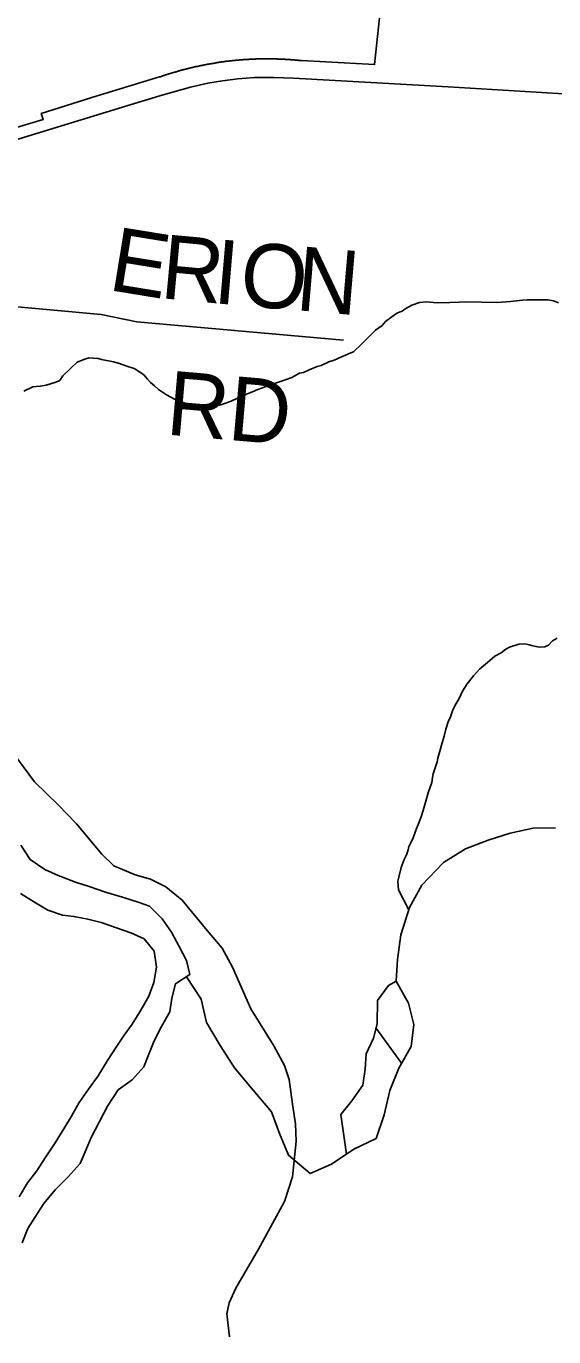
# Model space of a CAD drawing. Extents: x 0 to 34, y 0 to 22.
# Drawn here: x 5.777 to 6.245, y 15.409 to 16.571 of the extents above; entities that cross this region are included whole.
import ezdxf

# ---------------------------------------------------------------- set-up
doc = ezdxf.new("R2010")
doc.units = 0
for name, color, linetype in [('GM_X_Corporation', 7, 'Continuous'), ('GM_X_Major_River', 7, 'Continuous'), ('GM_X_Minor_River', 7, 'Continuous'), ('GM_X_Rail_Line', 7, 'Continuous'), ('GM_X_Township_Road', 7, 'Continuous'), ('GM_X_Township_Road_Text', 7, 'Continuous')]:
    doc.layers.add(name, color=color, linetype=linetype)

msp = doc.modelspace()

# ---------------------------------------------------------------- linework, layer by layer
at = {"layer": 'GM_X_Corporation'}
msp.add_lwpolyline([(6.0913, 16.5869), (6.0859, 16.5372), (6.0212, 16.5407), (6.0206, 16.5407), (6.02, 16.5408), (6.0193, 16.5409), (6.0187, 16.5409), (6.0181, 16.541), (6.0175, 16.541), (6.0169, 16.5411), (6.0163, 16.5412), (6.0156, 16.5412), (6.015, 16.5413), (6.0144, 16.5413), (6.0138, 16.5414), (6.0132, 16.5414), (6.0126, 16.5415), (6.0119, 16.5415), (6.0113, 16.5416), (6.0107, 16.5416), (6.0101, 16.5416), (6.0095, 16.5417), (6.0088, 16.5417), (6.0082, 16.5418), (6.0076, 16.5418), (6.007, 16.5418), (6.0064, 16.5419), (6.0058, 16.5419), (6.0051, 16.5419), (6.0045, 16.542), (6.0039, 16.542), (6.0033, 16.542), (6.0027, 16.5421), (6.002, 16.5421), (6.0014, 16.5421), (6.0008, 16.5421), (6.0002, 16.5421), (5.9996, 16.5422), (5.999, 16.5422), (5.9983, 16.5422), (5.9977, 16.5422), (5.9971, 16.5422), (5.9965, 16.5422), (5.9959, 16.5423), (5.9952, 16.5423), (5.9946, 16.5423), (5.994, 16.5423), (5.9934, 16.5423), (5.9928, 16.5423), (5.9921, 16.5423), (5.9915, 16.5423), (5.9909, 16.5423), (5.9903, 16.5423), (5.9897, 16.5423), (5.989, 16.5423), (5.9884, 16.5423), (5.9878, 16.5423), (5.9872, 16.5423), (5.9866, 16.5423), (5.986, 16.5423), (5.9853, 16.5423), (5.9847, 16.5423), (5.9841, 16.5422), (5.9835, 16.5422), (5.9829, 16.5422), (5.9822, 16.5422), (5.9816, 16.5422), (5.981, 16.5422), (5.9804, 16.5421), (5.9798, 16.5421), (5.9791, 16.5421), (5.9785, 16.5421), (5.9779, 16.542), (5.9773, 16.542), (5.9767, 16.542), (5.9761, 16.5419), (5.9754, 16.5419), (5.9748, 16.5419), (5.9742, 16.5418), (5.9736, 16.5418), (5.973, 16.5418), (5.9723, 16.5417), (5.9717, 16.5417), (5.9711, 16.5417), (5.9705, 16.5416), (5.9699, 16.5416), (5.9693, 16.5415), (5.9686, 16.5415), (5.968, 16.5414), (5.9674, 16.5414), (5.9668, 16.5413), (5.9662, 16.5413), (5.9656, 16.5412), (5.9649, 16.5412), (5.9643, 16.5411), (5.9637, 16.5411), (5.9631, 16.541), (5.9625, 16.5409), (5.9619, 16.5409), (5.9612, 16.5408), (5.9606, 16.5408), (5.96, 16.5407), (5.9594, 16.5406), (5.9588, 16.5406), (5.9582, 16.5405), (5.9575, 16.5404), (5.9569, 16.5403), (5.9563, 16.5403), (5.9557, 16.5402), (5.9551, 16.5401), (5.9545, 16.5401), (5.9539, 16.54), (5.9532, 16.5399), (5.9526, 16.5398), (5.952, 16.5397), (5.9514, 16.5396), (5.9508, 16.5396), (5.9502, 16.5395), (5.9496, 16.5394), (5.949, 16.5393), (5.9483, 16.5392), (5.9477, 16.5391), (5.9471, 16.539), (5.9465, 16.5389), (5.9459, 16.5388), (5.9453, 16.5387), (5.9447, 16.5386), (5.9441, 16.5385), (5.9434, 16.5384), (5.9428, 16.5383), (5.9422, 16.5382), (5.9416, 16.5381), (5.941, 16.538), (5.9404, 16.5379), (5.9398, 16.5378), (5.9392, 16.5377), (5.9386, 16.5376), (5.938, 16.5375), (5.9373, 16.5374), (5.9367, 16.5373), (5.9361, 16.5371), (5.9355, 16.537), (5.9349, 16.5369), (5.9343, 16.5368), (5.9337, 16.5367), (5.9331, 16.5365), (5.9325, 16.5364), (5.9319, 16.5363), (5.9313, 16.5362), (5.9307, 16.536), (5.9301, 16.5359), (5.9295, 16.5358), (5.9289, 16.5356), (5.9282, 16.5355), (5.9276, 16.5354), (5.927, 16.5352), (5.9264, 16.5351), (5.9258, 16.535), (5.9252, 16.5348), (5.9246, 16.5347), (5.924, 16.5345), (5.9234, 16.5344), (5.9228, 16.5343), (5.9222, 16.5341), (5.9216, 16.534), (5.921, 16.5338), (5.9204, 16.5337), (5.9198, 16.5335), (5.9192, 16.5334), (5.9186, 16.5332), (5.918, 16.533), (5.9174, 16.5329), (5.9168, 16.5327), (5.9162, 16.5326), (5.9156, 16.5324), (5.915, 16.5323), (5.9144, 16.5321), (5.9138, 16.5319), (5.9132, 16.5318), (5.9126, 16.5316), (5.912, 16.5314), (5.9114, 16.5313), (5.9109, 16.5311), (5.9103, 16.5309), (5.9097, 16.5307), (5.9091, 16.5306), (5.9085, 16.5304), (5.9079, 16.5302), (5.9073, 16.53), (5.9067, 16.5299), (5.9061, 16.5297), (5.9055, 16.5295), (5.9049, 16.5293), (5.9043, 16.5291), (5.9037, 16.5289), (5.9031, 16.5288), (5.9026, 16.5286), (5.902, 16.5284), (5.9014, 16.5282), (5.9008, 16.528), (5.9002, 16.5278), (5.8996, 16.5276), (5.899, 16.5274), (5.8984, 16.5272), (5.8979, 16.527), (5.8973, 16.5268), (5.8967, 16.5266), (5.8961, 16.5264), (5.8955, 16.5262), (5.8606, 16.5156), (5.8401, 16.5094), (5.7906, 16.4938), (5.7923, 16.4886), (5.6263, 16.4388)], dxfattribs=at)
at = {"layer": 'GM_X_Major_River'}
for points in [[(5.7725, 15.845), (5.7806, 15.8323), (5.7938, 15.8237), (5.8055, 15.8182), (5.821, 15.8123), (5.8331, 15.8086), (5.8474, 15.8035), (5.8625, 15.799), (5.8765, 15.7946), (5.8864, 15.791), (5.8976, 15.7798), (5.9061, 15.7679), (5.9127, 15.7553), (5.9194, 15.743), (5.9222, 15.7304), (5.9096, 15.7223), (5.9063, 15.7094), (5.9046, 15.6973), (5.8972, 15.6845), (5.8905, 15.6717), (5.8854, 15.6584), (5.8814, 15.6486), (5.871, 15.637), (5.8587, 15.6281), (5.8493, 15.6138), (5.8348, 15.586), (5.8305, 15.5754), (5.8249, 15.5629), (5.8145, 15.551), (5.8029, 15.5397), (5.7928, 15.5274), (5.785, 15.515), (5.7788, 15.5052), (5.7737, 15.4927)], [(5.7722, 15.8024), (5.7846, 15.7946), (5.7963, 15.7876), (5.8095, 15.7832), (5.8193, 15.7819), (5.8318, 15.7794), (5.8436, 15.7765), (5.8572, 15.7718), (5.87, 15.7674), (5.8817, 15.7622), (5.8906, 15.7511), (5.8927, 15.737), (5.8902, 15.7233), (5.8858, 15.7113), (5.8788, 15.6988), (5.871, 15.6864), (5.864, 15.6767), (5.8574, 15.6669), (5.8492, 15.6541), (5.841, 15.6406), (5.8325, 15.6289), (5.8243, 15.6169), (5.8173, 15.6049), (5.8114, 15.5951), (5.8028, 15.5812), (5.7939, 15.568), (5.7865, 15.5564), (5.7783, 15.5459), (5.7709, 15.5334)]]:
    msp.add_lwpolyline(points, dxfattribs=at)
at = {"layer": 'GM_X_Minor_River'}
for points in [[(5.8945, 16.2491), (5.9017, 16.2444), (5.9092, 16.2404), (5.9145, 16.2384), (5.919, 16.2365), (5.9255, 16.2352), (5.9316, 16.2347), (5.9361, 16.2343), (5.9392, 16.2342), (5.9449, 16.2345), (5.9498, 16.2355), (5.959, 16.2388), (5.9644, 16.2414), (5.9674, 16.2424), (5.9724, 16.245), (5.9778, 16.2472), (5.9824, 16.249), (5.9889, 16.2516), (5.9981, 16.2548), (6.0026, 16.2563), (6.0126, 16.2599), (6.0195, 16.2636), (6.0229, 16.2643), (6.0279, 16.2665), (6.0352, 16.2694), (6.0386, 16.2705), (6.0455, 16.2738), (6.0501, 16.2752), (6.0566, 16.2781), (6.0597, 16.2792), (6.0635, 16.2811), (6.0673, 16.2825), (6.0743, 16.2892), (6.0805, 16.2956), (6.0867, 16.3016), (6.0928, 16.306), (6.0955, 16.3094), (6.1013, 16.3135), (6.1063, 16.3172), (6.1105, 16.3186), (6.1136, 16.3208), (6.119, 16.3238), (6.1259, 16.3263), (6.1316, 16.327), (6.1414, 16.3261), (6.1528, 16.3262), (6.1608, 16.3265), (6.1669, 16.3268), (6.1947, 16.3263), (6.2065, 16.3272), (6.2171, 16.3282), (6.2213, 16.3285), (6.2285, 16.3287), (6.2396, 16.3285), (6.2445, 16.3277), (6.249, 16.3261)], [(5.7752, 16.2477), (5.7832, 16.2514), (5.7862, 16.2517), (5.7897, 16.252), (5.795, 16.2531), (5.8034, 16.2556), (5.8069, 16.2571), (5.8096, 16.2612), (5.8169, 16.2679), (5.8223, 16.2735), (5.8254, 16.2746), (5.8292, 16.276), (5.8327, 16.2771), (5.841, 16.2766), (5.8441, 16.2758), (5.8547, 16.2737), (5.86, 16.2721), (5.8656, 16.2701), (5.8728, 16.2677), (5.8785, 16.2642), (5.8818, 16.2618), (5.8848, 16.2583), (5.8874, 16.2553), (5.8908, 16.2525), (5.8945, 16.2491)], [(6.1163, 15.7879), (6.1072, 15.8055), (6.1066, 15.8131), (6.1074, 15.8169), (6.1095, 15.8252), (6.1122, 15.8324), (6.1142, 15.8366), (6.1158, 15.8411), (6.1162, 15.8441), (6.1198, 15.8509), (6.123, 15.86), (6.1246, 15.8634), (6.1273, 15.8702), (6.1289, 15.8758), (6.1314, 15.8842), (6.1334, 15.8914), (6.1366, 15.9008), (6.1374, 15.905), (6.1379, 15.9084), (6.1414, 15.919), (6.1419, 15.9224), (6.1439, 15.9284), (6.1459, 15.936), (6.1475, 15.9417), (6.1492, 15.9481), (6.1512, 15.9545), (6.1531, 15.959), (6.1551, 15.9643), (6.1575, 15.9692), (6.161, 15.9753), (6.1638, 15.9817), (6.1681, 15.9881), (6.1735, 15.9952), (6.1789, 16.0012), (6.1859, 16.0071), (6.1924, 16.0127), (6.1982, 16.0157), (6.2024, 16.019), (6.2055, 16.0208), (6.2139, 16.0234), (6.2192, 16.0236), (6.223, 16.0228), (6.2261, 16.022), (6.2291, 16.0212), (6.2321, 16.0208), (6.2367, 16.0211), (6.2401, 16.0225), (6.2436, 16.0263), (6.2478, 16.0288)], [(5.9193, 15.7285), (5.9323, 15.7085), (5.9369, 15.688), (5.949, 15.6675), (5.9619, 15.6477), (5.9783, 15.628), (5.9946, 15.6086), (6.0018, 15.5896), (6.0098, 15.5702), (6.0288, 15.5539), (6.0478, 15.5623), (6.0675, 15.5756), (6.0873, 15.5851), (6.0945, 15.606), (6.0994, 15.6276), (6.1074, 15.6474), (6.1184, 15.6667), (6.1207, 15.6861), (6.1161, 15.7051), (6.1051, 15.7245), (6.1062, 15.7439), (6.1093, 15.7655), (6.1169, 15.7898), (6.1279, 15.8096), (6.1469, 15.8297), (6.1666, 15.8419), (6.1867, 15.8495), (6.2061, 15.8559), (6.2266, 15.8601), (6.2464, 15.8605)], [(6.1051, 15.7245), (6.0983, 15.7206), (6.0885, 15.7075), (6.0882, 15.6866), (6.0849, 15.6741), (6.0786, 15.6602), (6.0776, 15.6465), (6.0755, 15.6325), (6.0657, 15.6186), (6.056, 15.6063), (6.061, 15.5712)], [(6.0872, 15.6831), (6.1099, 15.6519)]]:
    msp.add_lwpolyline(points, dxfattribs=at)
at = {"layer": 'GM_X_Rail_Line'}
msp.add_lwpolyline([(5.6339, 16.4293), (5.8702, 16.5017), (5.8987, 16.5105), (5.9227, 16.5171), (5.9382, 16.5206), (5.9512, 16.5228), (5.9649, 16.5246), (5.9795, 16.5257), (5.9965, 16.5258), (6.014, 16.5251), (6.1512, 16.5176), (6.278, 16.5099)], dxfattribs=at)
at = {"layer": 'GM_X_Township_Road'}
for points in [[(5.4271, 16.3518), (5.4437, 16.351), (5.7078, 16.328), (5.8436, 16.3155), (5.8752, 16.3092), (6.0583, 16.2929)], [(5.9575, 15.4091), (5.9551, 15.4295), (5.9571, 15.4394), (5.963, 15.4525), (5.9831, 15.4871), (6.006, 15.5291), (6.0131, 15.5511), (6.0166, 15.5827), (6.016, 15.5982), (6.0131, 15.6155), (6.0102, 15.6375), (6.006, 15.6497), (5.9967, 15.6673), (5.9764, 15.7), (5.96, 15.7371), (5.951, 15.7538), (5.9377, 15.7696), (5.9155, 15.7964), (5.901, 15.8082), (5.8874, 15.815), (5.8738, 15.8187), (5.855, 15.8267), (5.8442, 15.8372), (5.8219, 15.8641), (5.8056, 15.881), (5.7847, 15.9013), (5.7645, 15.9286)]]:
    msp.add_lwpolyline(points, dxfattribs=at)

# ---------------------------------------------------------------- texts
at = {"layer": 'GM_X_Township_Road_Text'}
for s, height, rotation, p in [('E', 0.0568, 350.7547, (5.8489, 16.3375)), ('R', 0.0568, 354.7188, (5.8951, 16.3302)), ('I', 0.0568, 355.0978, (5.942, 16.3258)), ('O', 0.0568, 355.0945, (5.9653, 16.3238)), ('N', 0.0568, 355.0908, (6.0151, 16.3196)), ('RD', 0.05682, 355.0738, (5.9002, 16.2093))]:
    msp.add_text(s, height=height, rotation=rotation, dxfattribs=at).set_placement(p)

doc.saveas('drawing.dxf')
